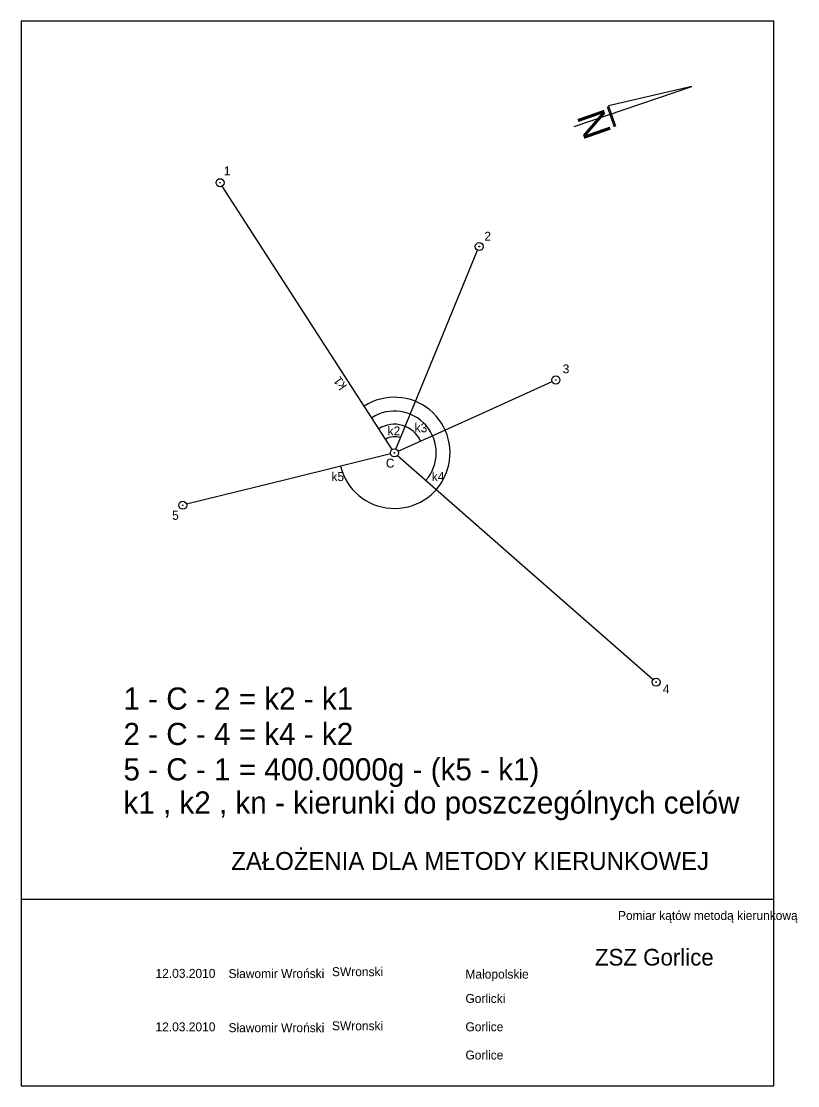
# Model space of a CAD drawing. Extents: x 4638556 to 4640059, y 5351940 to 5352237.
# Drawn here: x 4639842.6 to 4640059.4, y 5351939.6 to 5352236.6 of the extents above; entities that cross this region are included whole.
import ezdxf

# ---------------------------------------------------------------- set-up
doc = ezdxf.new("R2010")
doc.units = 0
doc.layers.add('Default', color=7, linetype='Continuous')

msp = doc.modelspace()

# ---------------------------------------------------------------- linework, layer by layer
at = {"layer": 'Default'}
for p, q in [((4639996.98, 5352207.23), (4640029.78, 5352218.39)), ((4640029.78, 5352218.39), (4640006.56, 5352213.04)), ((4640006.16, 5352212.85), (4640008.15, 5352207.17)), ((4640006.56, 5352213.04), (4640008.54, 5352207.36)), ((4639922.46, 5352153.89), (4639898.73, 5352190.65)), ((4639958.83, 5352145.5), (4639970.02, 5352172.74)), ((4639946.19, 5352117.14), (4639922.46, 5352153.89)), ((4639947.22, 5352117.23), (4639958.83, 5352145.5)), ((4639969.32, 5352126.36), (4639990.82, 5352136.07)), ((4639947.81, 5352116.66), (4639969.32, 5352126.36)), ((4639945.71, 5352115.93), (4639917.25, 5352108.88)), ((4639947.65, 5352115.48), (4639983.32, 5352084.22)), ((4639917.25, 5352108.88), (4639888.8, 5352101.84)), ((4639983.32, 5352084.22), (4640018.99, 5352052.95))]:
    msp.add_line(p, q, dxfattribs=at)
for points in [[(4639842.64, 5351939.61), (4640052.64, 5351939.61), (4640052.64, 5352236.61), (4639842.64, 5352236.61)], [(4639842.64, 5351939.61), (4640052.64, 5351939.61), (4640052.64, 5351991.61), (4639842.64, 5351991.61)]]:
    msp.add_lwpolyline(points, close=True, dxfattribs=at)
for centre, radius in [((4639898.13, 5352191.58), 1.12), ((4639898.13, 5352191.58), 0.0804), ((4639970.45, 5352173.77), 1.12), ((4639970.45, 5352173.77), 0.0804), ((4639991.84, 5352136.52), 1.12), ((4639991.84, 5352136.52), 0.0804), ((4639946.8, 5352116.2), 1.12), ((4639946.8, 5352116.2), 0.0804), ((4639887.71, 5352101.57), 1.12), ((4639887.71, 5352101.57), 0.0804), ((4640019.83, 5352052.21), 1.12), ((4640019.83, 5352052.21), 0.0804)]:
    msp.add_circle(centre, radius, dxfattribs=at)
for radius, start in [(15.51, 193.9113), (11.66, 318.8815), (7.98, 24.287), (4.51, 67.6678)]:
    msp.add_arc((4639946.8, 5352116.2), radius, start, 122.8465, dxfattribs=at)

# ---------------------------------------------------------------- texts
for s, height, rotation, p in [('N', 7.81, 289.2401, (4639997.59, 5352210.14)), ('k1', 2.5, 126.0823, (4639933.67, 5352134.92))]:
    msp.add_text(s, height=height, rotation=rotation, dxfattribs=at).set_placement(p)
for s, height, p in [('1', 2.5, (4639899.17, 5352193.62)), ('2', 2.5, (4639971.89, 5352175.37)), ('3', 2.5, (4639993.75, 5352138.38)), ('k3', 2.5, (4639952.43, 5352121.95)), ('k2', 2.5, (4639944.89, 5352121.06)), ('C', 2.5, (4639944.4, 5352112.08)), ('k5', 2.5, (4639929.21, 5352108.32)), ('k4', 2.5, (4639957.2, 5352108.32)), ('5', 2.5, (4639884.75, 5352097.52)), ('1 - C - 2 = k2 - k1', 6.1855, (4639871.16, 5352044.54)), ('4', 2.5, (4640021.71, 5352049.06)), ('2 - C - 4 = k4 - k2', 6.1855, (4639871.16, 5352034.67)), ('5 - C - 1 = 400.0000g - (k5 - k1)', 6.1855, (4639871.16, 5352024.8)), ('k1 , k2 , kn - kierunki do poszczególnych celów', 6.1855, (4639871.16, 5352015.54)), ('ZAŁOŻENIA DLA METODY KIERUNKOWEJ', 5, (4639901.24, 5351999.82)), ('Pomiar kątów metodą kierunkową', 2.5, (4640009.18, 5351985.86)), ('ZSZ Gorlice', 4.6473, (4640002.76, 5351973.14)), ('SWronski', 2.5, (4639929.36, 5351970.18)), ('12.03.2010', 2.5, (4639880.1, 5351969.71)), ('Sławomir Wroński', 2.5, (4639900.48, 5351969.65)), ('Małopolskie', 2.5, (4639966.61, 5351969.5)), ('Gorlicki', 2.5, (4639966.61, 5351962.7)), ('12.03.2010', 2.5, (4639880.1, 5351954.79)), ('Sławomir Wroński', 2.5, (4639900.48, 5351954.55)), ('SWronski', 2.5, (4639929.36, 5351955.08)), ('Gorlice', 2.5, (4639966.61, 5351954.81)), ('Gorlice', 2.5, (4639966.61, 5351946.92))]:
    msp.add_text(s, height=height, dxfattribs=at).set_placement(p)

doc.saveas('drawing.dxf')
